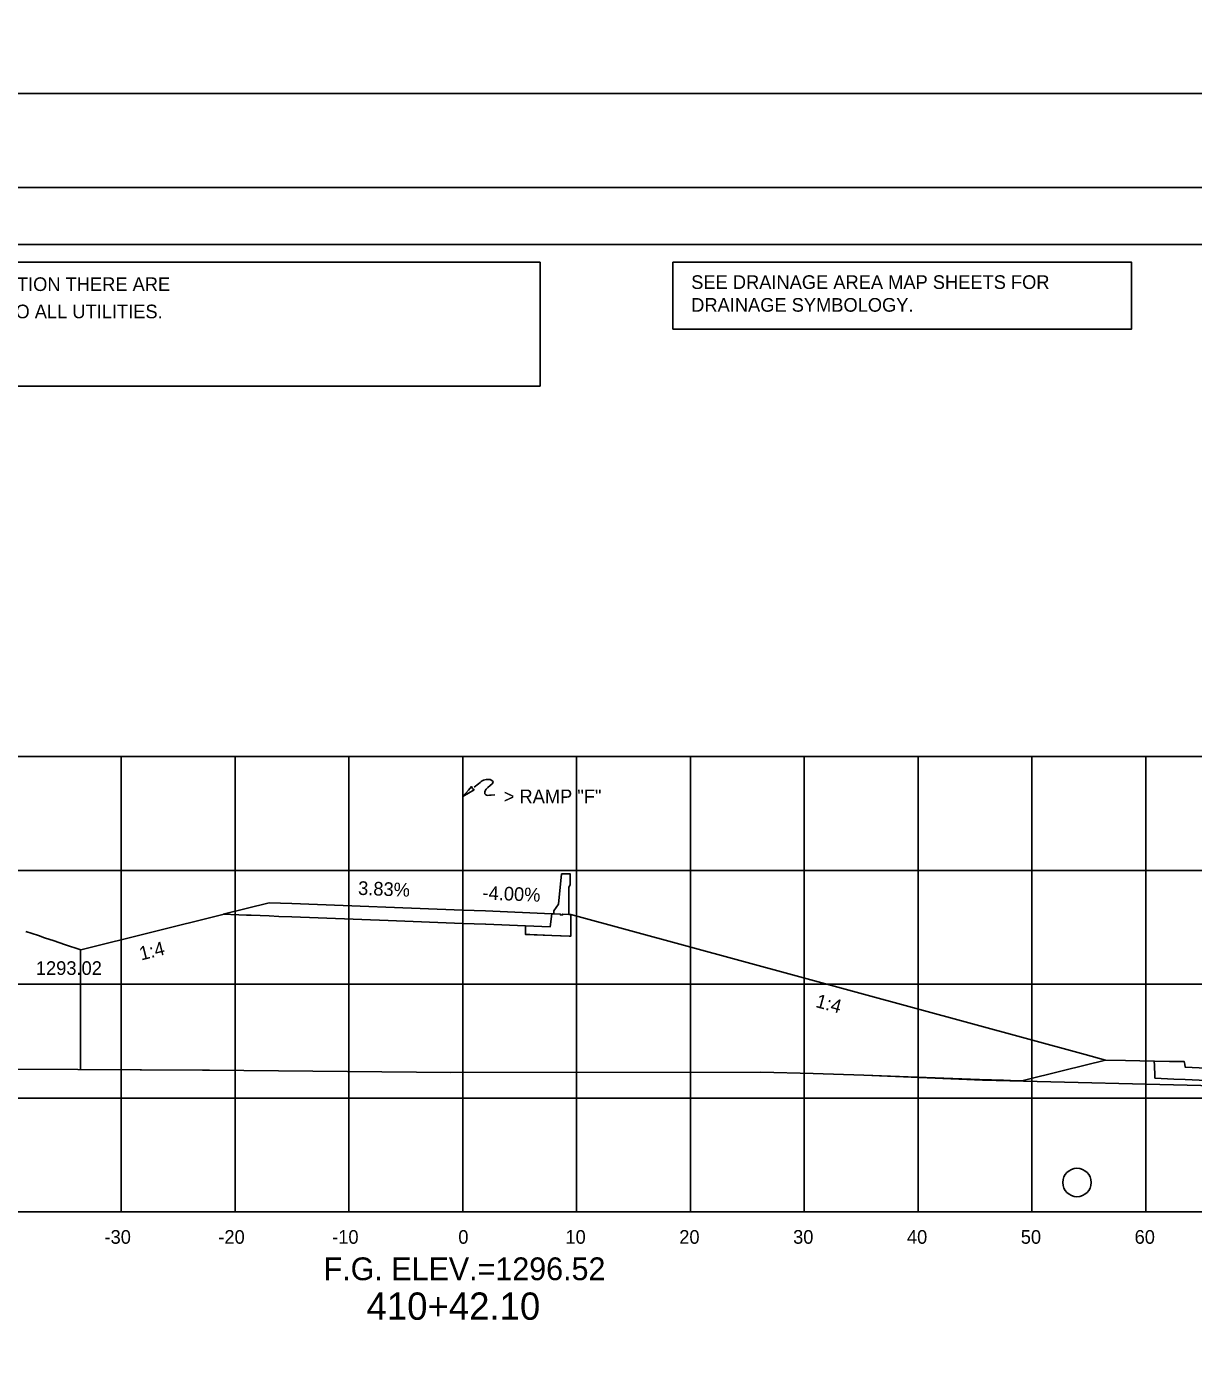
# Model space of a CAD drawing. Extents: x 2148105 to 2149976, y 144169 to 149705.
# Drawn here: x 2148375 to 2148477.5, y 145273.3 to 145391 of the extents above; entities that cross this region are included whole.
import ezdxf

# ---------------------------------------------------------------- set-up
doc = ezdxf.new("R2010")
doc.units = 0
for name, color, linetype in [('Bridge M-Header', 7, 'Continuous'), ('Default', 7, 'Continuous'), ('EX_Align', 7, 'Continuous'), ('INR_Tracking', 7, 'Continuous'), ('Ph1-PR-Ramp SF3 Rev-Curb', 7, 'Continuous'), ('PH1a-2-RampC', 7, 'Continuous'), ('PH1a-PR-DividingStrip', 7, 'Continuous'), ('PH1a-PR-ServRd', 7, 'Continuous'), ('PH2-PR-Barrier', 7, 'Continuous'), ('PR-ApproachSlab', 7, 'Continuous'), ('PR-SHLDR-RMP-H', 7, 'Continuous'), ('PR_Align_Ramp_E', 7, 'Continuous'), ('PR_Align_Ramp_J', 7, 'Continuous'), ('PR_Storm_Channel', 7, 'Continuous'), ('PR_Storm_Conc_Box_PH1B', 7, 'Continuous'), ('PR_Storm_Conc_Pipe_PH1B', 7, 'Continuous'), ('PR_Storm_Inlet_CICI_PH1A', 7, 'Continuous'), ('PR_Storm_Inlet_CICI_PH1B', 7, 'Continuous'), ('PR_Storm_Junction_Box_PH1B', 7, 'Continuous'), ('PR_Storm_MH', 7, 'Continuous'), ('PR_Storm_MH_PH1B', 7, 'Continuous'), ('PR_Storm_Standard_Median_Drain_PH1B', 7, 'Continuous'), ('TopCut', 7, 'Continuous')]:
    doc.layers.add(name, color=color, linetype=linetype)

# ---------------------------------------------------------------- blocks, each defined once
blk = doc.blocks.new('POINT_DISPLAY')
at = {"layer": 'Default'}
blk.add_line((0, 0), (0, 0), dxfattribs=at)

msp = doc.modelspace()

# ---------------------------------------------------------------- linework, layer by layer
at = {"layer": 'EX_Align'}
msp.add_lwpolyline([(2148374.95, 145311.55), (2148376.04, 145311.18), (2148376.59, 145310.99), (2148377.42, 145310.72), (2148378.34, 145310.4), (2148379.76, 145309.93)], dxfattribs=at)
at = {"layer": 'INR_Tracking'}
msp.add_lwpolyline([(2148379.75, 145309.93), (2148379.76, 145309.93), (2148392.25, 145313.05), (2148392.28, 145313.06), (2148394.32, 145312.98), (2148394.33, 145312.98), (2148394.33, 145312.98), (2148394.73, 145312.97), (2148396.32, 145312.91), (2148397.16, 145312.87), (2148398.32, 145312.83), (2148406.76, 145312.51), (2148413.32, 145312.26), (2148413.33, 145312.25), (2148415.32, 145312.18), (2148415.34, 145312.18), (2148418.82, 145312.04), (2148418.82, 145312.04), (2148418.82, 145311.72), (2148418.83, 145311.29), (2148418.83, 145311.29), (2148419.22, 145311.27), (2148421.15, 145311.2), (2148422.66, 145311.13), (2148422.81, 145311.13), (2148422.81, 145311.53), (2148422.82, 145311.88), (2148422.82, 145312.28), (2148422.83, 145313.05), (2148468, 145300.73), (2148469.77, 145300.24), (2148469.77, 145300.24)], dxfattribs=at)
at = {"layer": 'Ph1-PR-Ramp SF3 Rev-Curb'}
msp.add_circle((2148467.28, 145289.49), 1.25, dxfattribs=at)
at = {"layer": 'PH1a-PR-ServRd'}
msp.add_lwpolyline([(2148570.82, 145161.91), (2148255.82, 145161.91), (2148255.82, 145371.91), (2148570.82, 145371.91)], close=True, dxfattribs=at)
at = {"layer": 'PH2-PR-Barrier'}
msp.add_line((2148413.32, 145313.42), (2148413.32, 145323.42), dxfattribs=at)
for points in [[(2148414.33, 145324.23), (2148414.69, 145324.52), (2148414.85, 145324.65), (2148414.94, 145324.73), (2148415.04, 145324.78), (2148415.14, 145324.83), (2148415.26, 145324.87), (2148415.39, 145324.9), (2148415.49, 145324.91), (2148415.57, 145324.91), (2148415.65, 145324.9), (2148415.72, 145324.89), (2148415.78, 145324.87), (2148415.83, 145324.85), (2148415.87, 145324.82), (2148415.91, 145324.79), (2148415.95, 145324.75), (2148415.98, 145324.69), (2148415.97, 145324.63), (2148415.96, 145324.6), (2148415.91, 145324.53), (2148415.72, 145324.36), (2148415.53, 145324.2), (2148415.46, 145324.13), (2148415.39, 145324.05), (2148415.33, 145323.96), (2148415.29, 145323.89), (2148415.25, 145323.81), (2148415.25, 145323.73), (2148415.27, 145323.64), (2148415.31, 145323.58), (2148415.36, 145323.54), (2148415.42, 145323.52), (2148415.53, 145323.5), (2148415.66, 145323.51), (2148415.82, 145323.52), (2148416.15, 145323.56)], [(2148413.32, 145323.42), (2148413.84, 145323.97), (2148414.1, 145324.28), (2148414.18, 145324.11), (2148414.32, 145324), (2148413.32, 145323.42)]]:
    msp.add_lwpolyline(points, dxfattribs=at)
at = {"layer": 'PR-ApproachSlab'}
msp.add_lwpolyline([(2148462.44, 145298.41), (2148466.08, 145299.32), (2148469.77, 145300.24), (2148471.54, 145300.21), (2148474.07, 145300.16), (2148475.42, 145300.13), (2148476.11, 145300.12), (2148476.12, 145300.12), (2148476.12, 145300.12), (2148476.45, 145300.12), (2148476.7, 145300.12), (2148476.74, 145299.89), (2148476.79, 145299.62), (2148476.79, 145299.62), (2148482.94, 145299.33)], dxfattribs=at)
at = {"layer": 'PR-SHLDR-RMP-H'}
msp.add_lwpolyline([(2148462.44, 145298.41), (2148466.08, 145299.32), (2148469.77, 145300.24), (2148471.54, 145300.21), (2148474.07, 145300.16), (2148474.07, 145300.08), (2148474.08, 145299.82), (2148474.09, 145299.82), (2148474.09, 145299.82), (2148474.09, 145299.64), (2148474.11, 145298.99), (2148474.12, 145298.92), (2148474.12, 145298.66), (2148475.8, 145298.58), (2148476.79, 145298.54), (2148476.79, 145298.54), (2148482.94, 145298.25)], dxfattribs=at)
at = {"layer": 'PR_Align_Ramp_E'}
for points in [[(2148219.95, 145625.16), (2148579.95, 145625.16), (2148579.95, 145385.16), (2148219.95, 145385.16)], [(2148219.95, 145385.16), (2148579.95, 145385.16), (2148579.95, 145145.16), (2148219.95, 145145.16)]]:
    msp.add_lwpolyline(points, close=True, dxfattribs=at)
at = {"layer": 'PR_Align_Ramp_J'}
msp.add_lwpolyline([(2148236.32, 145376.91), (2148576.32, 145376.91), (2148576.32, 145156.91), (2148236.32, 145156.91)], close=True, dxfattribs=at)
at = {"layer": 'PR_Storm_Channel'}
msp.add_lwpolyline([(2148392.27, 145313.06), (2148396.32, 145314.07), (2148398.32, 145314), (2148413.32, 145313.42), (2148415.32, 145313.35), (2148421.15, 145313.11)], dxfattribs=at)
at = {"layer": 'PR_Storm_Conc_Box_PH1B'}
for p, q in [((2148263.32, 145326.91), (2148563.32, 145326.91)), ((2148383.32, 145286.91), (2148383.32, 145326.91)), ((2148393.32, 145286.91), (2148393.32, 145326.91)), ((2148403.32, 145286.91), (2148403.32, 145326.91)), ((2148413.32, 145286.91), (2148413.32, 145326.91)), ((2148423.32, 145286.91), (2148423.32, 145326.91)), ((2148433.32, 145286.91), (2148433.32, 145326.91)), ((2148443.32, 145286.91), (2148443.32, 145326.91)), ((2148453.32, 145286.91), (2148453.32, 145326.91)), ((2148463.32, 145286.91), (2148463.32, 145326.91)), ((2148473.32, 145286.91), (2148473.32, 145326.91)), ((2148263.32, 145316.91), (2148563.32, 145316.91)), ((2148263.32, 145306.91), (2148563.32, 145306.91)), ((2148263.32, 145296.91), (2148563.32, 145296.91)), ((2148263.32, 145286.91), (2148563.32, 145286.91))]:
    msp.add_line(p, q, dxfattribs=at)
at = {"layer": 'PR_Storm_Conc_Pipe_PH1B'}
msp.add_lwpolyline([(2148255.82, 145161.91), (2148570.82, 145161.91), (2148570.82, 145371.91), (2148255.82, 145371.91)], close=True, dxfattribs=at)
msp.add_lwpolyline([(2148255.82, 145161.91), (2148570.82, 145161.91), (2148570.82, 145371.91), (2148255.82, 145371.91)], close=True, dxfattribs=at)
at = {"layer": 'PR_Storm_Inlet_CICI_PH1A'}
for points in [[(2148422.64, 145313.05), (2148422.63, 145315.41), (2148422.76, 145315.68), (2148422.76, 145316.61), (2148422.01, 145316.61), (2148421.73, 145313.94), (2148421.33, 145313.36), (2148421.32, 145313.11), (2148421.9, 145313.08), (2148421.9, 145313), (2148422.08, 145312.99), (2148422.08, 145313.08)], [(2148422.81, 145311.13), (2148421.15, 145311.2), (2148418.83, 145311.29), (2148418.82, 145312.04), (2148420.99, 145311.95), (2148421.15, 145313.11), (2148421.32, 145313.11), (2148421.9, 145313.08), (2148421.9, 145313), (2148422.08, 145312.99), (2148422.08, 145313.08), (2148422.64, 145313.05), (2148422.83, 145313.05), (2148422.82, 145311.88)]]:
    msp.add_lwpolyline(points, close=True, dxfattribs=at)
at = {"layer": 'PR_Storm_Inlet_CICI_PH1B'}
msp.add_lwpolyline([(2148363.01, 145299.52), (2148390.47, 145299.37), (2148390.52, 145299.37), (2148390.77, 145299.37), (2148391.07, 145299.36), (2148412.27, 145299.16), (2148439.52, 145299.2), (2148444.09, 145299.07), (2148448.54, 145298.93), (2148458.98, 145298.49), (2148480.56, 145297.97), (2148482.92, 145297.92), (2148483.97, 145297.9), (2148492.66, 145297.82), (2148497.42, 145297.71), (2148510.43, 145297.55), (2148512.24, 145297.53), (2148512.35, 145297.53), (2148517.25, 145297.46), (2148539.38, 145297.15), (2148541.2, 145297.15), (2148547.25, 145297.09), (2148558.65, 145296.99), (2148563.32, 145297.04)], dxfattribs=at)
at = {"layer": 'PR_Storm_MH'}
for points in [[(2148257.69, 145370.34), (2148420.12, 145370.34), (2148420.12, 145359.47), (2148257.69, 145359.47)], [(2148431.78, 145370.34), (2148472.07, 145370.34), (2148472.07, 145364.47), (2148431.78, 145364.47)]]:
    msp.add_lwpolyline(points, close=True, dxfattribs=at)
at = {"layer": 'PR_Storm_Standard_Median_Drain_PH1B'}
msp.add_line((2148263.32, 145286.91), (2148563.32, 145286.91), dxfattribs=at)
at = {"layer": 'TopCut'}
msp.add_lwpolyline([(2148379.75, 145309.93), (2148379.75, 145299.43), (2148390.47, 145299.37), (2148390.52, 145299.37), (2148390.77, 145299.37), (2148391.07, 145299.36), (2148412.27, 145299.16), (2148439.52, 145299.2), (2148444.09, 145299.07), (2148448.54, 145298.93), (2148458.71, 145298.55), (2148460.83, 145298.47), (2148462.08, 145298.42), (2148462.44, 145298.41), (2148466.08, 145299.32), (2148469.77, 145300.24), (2148469.77, 145300.24), (2148468, 145300.73), (2148422.83, 145313.05), (2148422.82, 145312.28), (2148422.82, 145311.88), (2148422.81, 145311.53), (2148422.81, 145311.13), (2148421.15, 145311.2), (2148418.83, 145311.29), (2148418.82, 145312.04), (2148415.34, 145312.18), (2148415.32, 145312.18), (2148413.33, 145312.25), (2148413.32, 145312.26), (2148406.76, 145312.51), (2148398.32, 145312.83), (2148397.16, 145312.87), (2148396.32, 145312.91), (2148394.73, 145312.97), (2148394.33, 145312.98), (2148394.33, 145312.98), (2148394.32, 145312.98), (2148392.28, 145313.06), (2148392.25, 145313.05), (2148379.76, 145309.93)], close=True, dxfattribs=at)

# ---------------------------------------------------------------- block references
at = {"layer": 'PR_Storm_Conc_Pipe_PH1B', "xscale": 10, "yscale": 10}
for p in [(2148398.32, 145314), (2148398.32, 145314), (2148415.32, 145313.35), (2148415.32, 145313.35), (2148421.15, 145313.11), (2148421.15, 145313.11)]:
    msp.add_blockref('POINT_DISPLAY', p, dxfattribs=at)

# ---------------------------------------------------------------- texts
at = {"layer": 'Bridge M-Header'}
for s, rotation, p in [('3.83%', 357.8095, (2148404.11, 145314.77)), ('-4.00%', 357.7094, (2148415.04, 145314.36))]:
    msp.add_text(s, height=1.2, rotation=rotation, dxfattribs=at).set_placement(p)
at = {"layer": 'PH1a-2-RampC'}
msp.add_text('1293.02', height=1.2, dxfattribs=at).set_placement((2148375.82, 145307.73))
at = {"layer": 'PH1a-PR-DividingStrip'}
for rotation, p in [(14.0365, (2148385.07, 145308.99)), (344.7446, (2148444.25, 145304.92))]:
    msp.add_text('1:4', height=1.2, rotation=rotation, dxfattribs=at).set_placement(p)
at = {"layer": 'PH2-PR-Barrier'}
msp.add_text('> RAMP "F"', height=1.2, rotation=360, dxfattribs=at).set_placement((2148416.92, 145322.82))
at = {"layer": 'PR_Storm_Junction_Box_PH1B'}
msp.add_text('410+42.10', height=2.4, dxfattribs=at).set_placement((2148404.87, 145277.43))
at = {"layer": 'PR_Storm_MH'}
for s, p in [('SEE DRAINAGE AREA MAP SHEETS FOR', (2148433.39, 145368)), ("(CAUTION) THE LOCATION OF ALL UTILITIES AS SHOWN ARE APPROXIMATE. DUE TO RELOCATION'S PLANNED OR PRESENTLY UNDER CONSTRUCTION THERE ARE ", (2148258.92, 145367.82)), ('DRAINAGE SYMBOLOGY.', (2148433.39, 145366)), ('SOME UTILITIES THAT WILL BE RELOCATED AND NOT SHOWN ON THESE PLANS. THE CONTRACTOR SHALL BE RESPONSIBLE FOR ANY DAMAGE TO ALL UTILITIES.', (2148258.92, 145365.42))]:
    msp.add_text(s, height=1.2, dxfattribs=at).set_placement(p)
at = {"layer": 'PR_Storm_MH_PH1B'}
for s, height, p in [('-30', 1.2, (2148381.85, 145284.11)), ('-20', 1.2, (2148391.85, 145284.11)), ('-10', 1.2, (2148401.85, 145284.11)), ('0', 1.2, (2148412.93, 145284.11)), ('10', 1.2, (2148422.34, 145284.11)), ('20', 1.2, (2148432.34, 145284.11)), ('30', 1.2, (2148442.34, 145284.11)), ('40', 1.2, (2148452.34, 145284.11)), ('50', 1.2, (2148462.34, 145284.11)), ('60', 1.2, (2148472.34, 145284.11)), ('F.G. ELEV.=1296.52', 2, (2148401.1, 145280.91))]:
    msp.add_text(s, height=height, dxfattribs=at).set_placement(p)

doc.saveas('drawing.dxf')
